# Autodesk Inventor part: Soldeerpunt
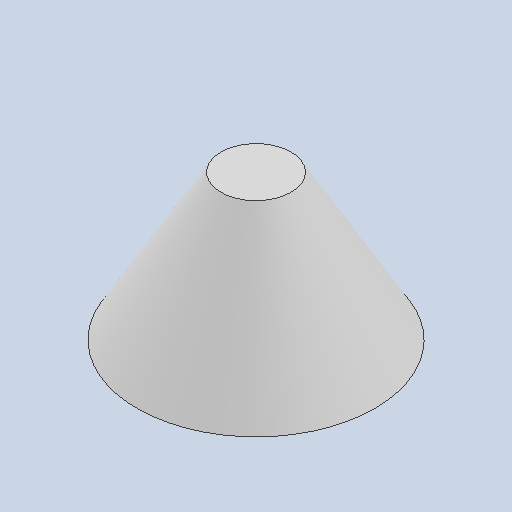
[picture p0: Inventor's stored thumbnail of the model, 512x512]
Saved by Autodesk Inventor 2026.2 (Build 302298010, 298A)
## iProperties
Created: 2023-02
Part Number: Soldeerpunt
Material: Generic
Document SubType Name: Modeling
Designer: mel
Density: 1 g/cm^3
Appearance: Par défaut
Author: mel
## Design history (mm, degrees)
feature "Solid1"
node "Solide1"
